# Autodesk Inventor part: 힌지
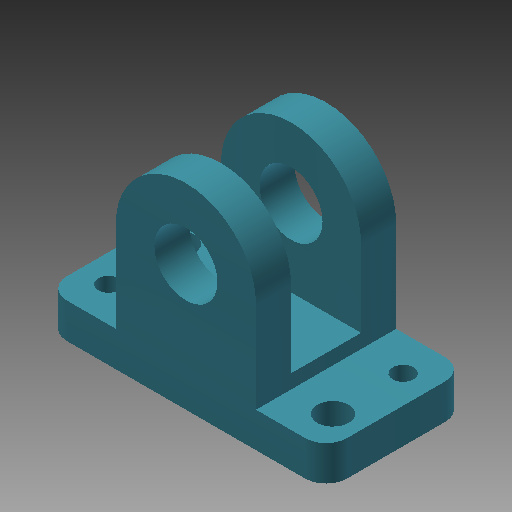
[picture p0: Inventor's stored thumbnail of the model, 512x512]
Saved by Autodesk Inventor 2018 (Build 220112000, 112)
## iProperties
Created: 2019-09
Part Number: 힌지
Material: 알루미늄 6061
Document SubType Name: Modeling
Designer: mduedu
Density: 2.71 g/cm^3
Appearance: 커뎃 파란색
Mass: 20.7756 g
Surface Area: 43.3328 cm^2
Volume: 7.66627 cm^3
Author: mduedu
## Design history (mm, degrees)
sketch "스케치1"
  geometry: L1 (-20, 0)-(20, 0); L2 (20, 0)-(20, 5); L3 (-20, 5)-(-20, 0); L4 (10, 5)-(10, 18); L5 (-10, 18)-(-10, 5); L6 (20, 5)-(10, 5); L7 (-10, 5)-(-20, 5); C1 r 4.5 at (0, 18); A1 r 10 centre (0, 18) between (10, 18) and (-10, 18); 2 further points
  constraints: 14 end point, 4 parallel, 2 centre point, 2 coincident, 2 point on circle, 2 tangent, 1 collinear, 1 horizontal, 1 midpoint, 1 perpendicular, 1 vertical, 1 vertical alignment
  dimensions: "d0" = 40 distance of L1.start L1.end; "d2" = 20 distance between parallel lines of L4 L5; "d3" = 18 distance from line of L1 A1.centre; "d4" = 5 distance of L1.end L2.end; "d5" = 9 diameter of C1
extrude "돌출1" new body sketch "스케치1" stored distance "d6" = 20; taper "d7" = 0 deg
sketch "스케치2"
  geometry: L1 (7, 5)-(37, 5); L2 (37, 5)-(37, -5); L3 (37, -5)-(7, -5); L4 (7, -5)-(7, 5); L5 (0, 10)-(0, -10) reference; 2 further points
  constraints: 8 end point, 2 parallel, 1 horizontal, 1 horizontal alignment, 1 midpoint, 1 perpendicular
  dimensions: "d8" = 7 distance between parallel lines of L5 L4; "d9" = 10 distance of L1.end L2.end; "d10" = 30 distance of L2.end L3.end
extrude "돌출2" cut sketch "스케치2" extent not by distance; stored distance "d11" = 20; taper "d12" = 0 deg
sketch "스케치3"
  geometry: 3 further points
  dimensions: "d13" = 16 horizontal distance of point (6, 15) point (-10, 10); "d14" = 32 horizontal distance of point (-26, 5) point (6, 15); "d15" = 5 vertical distance of point (6, 15) point (-10, 10); "d16" = 10 vertical distance of point (-26, 5) point (6, 15)
hole "구멍1" sketch "스케치3" at (6, 15), (-26, 5) diameter "d17" = 3; stored, may be unused: countersink angle "d21" = 90 deg, drill point angle "d23" = 118 deg; dims "d18" = 6, "d19" = 4, "d20" = 2, "d22" = 8
sketch "스케치4"
  geometry: C1 r 1.5 at (6, 15) reference; C2 r 1.5 at (-26, 5) reference; 3 further points
  constraints: 2 horizontal alignment, 2 vertical alignment
hole "구멍2" sketch "스케치4" at (-26, 15), (6, 5) diameter "d24" = 4.5; stored, may be unused: countersink angle "d28" = 90 deg, drill point angle "d30" = 118 deg; dims "d25" = 6, "d26" = 4, "d27" = 2, "d29" = 8
fillet "모깎기1" dims "d31" = 3
node "솔리드1"
